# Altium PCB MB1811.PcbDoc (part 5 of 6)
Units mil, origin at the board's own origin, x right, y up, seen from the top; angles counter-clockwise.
Board outline 3480.3 x 4291.34 mil, 4 copper layers (Top Layer, L2_VCC, L3_GND, Bottom Layer), stack 30.59 mil thick; 371 components, 285 nets, 1369 pads, 606 vias.
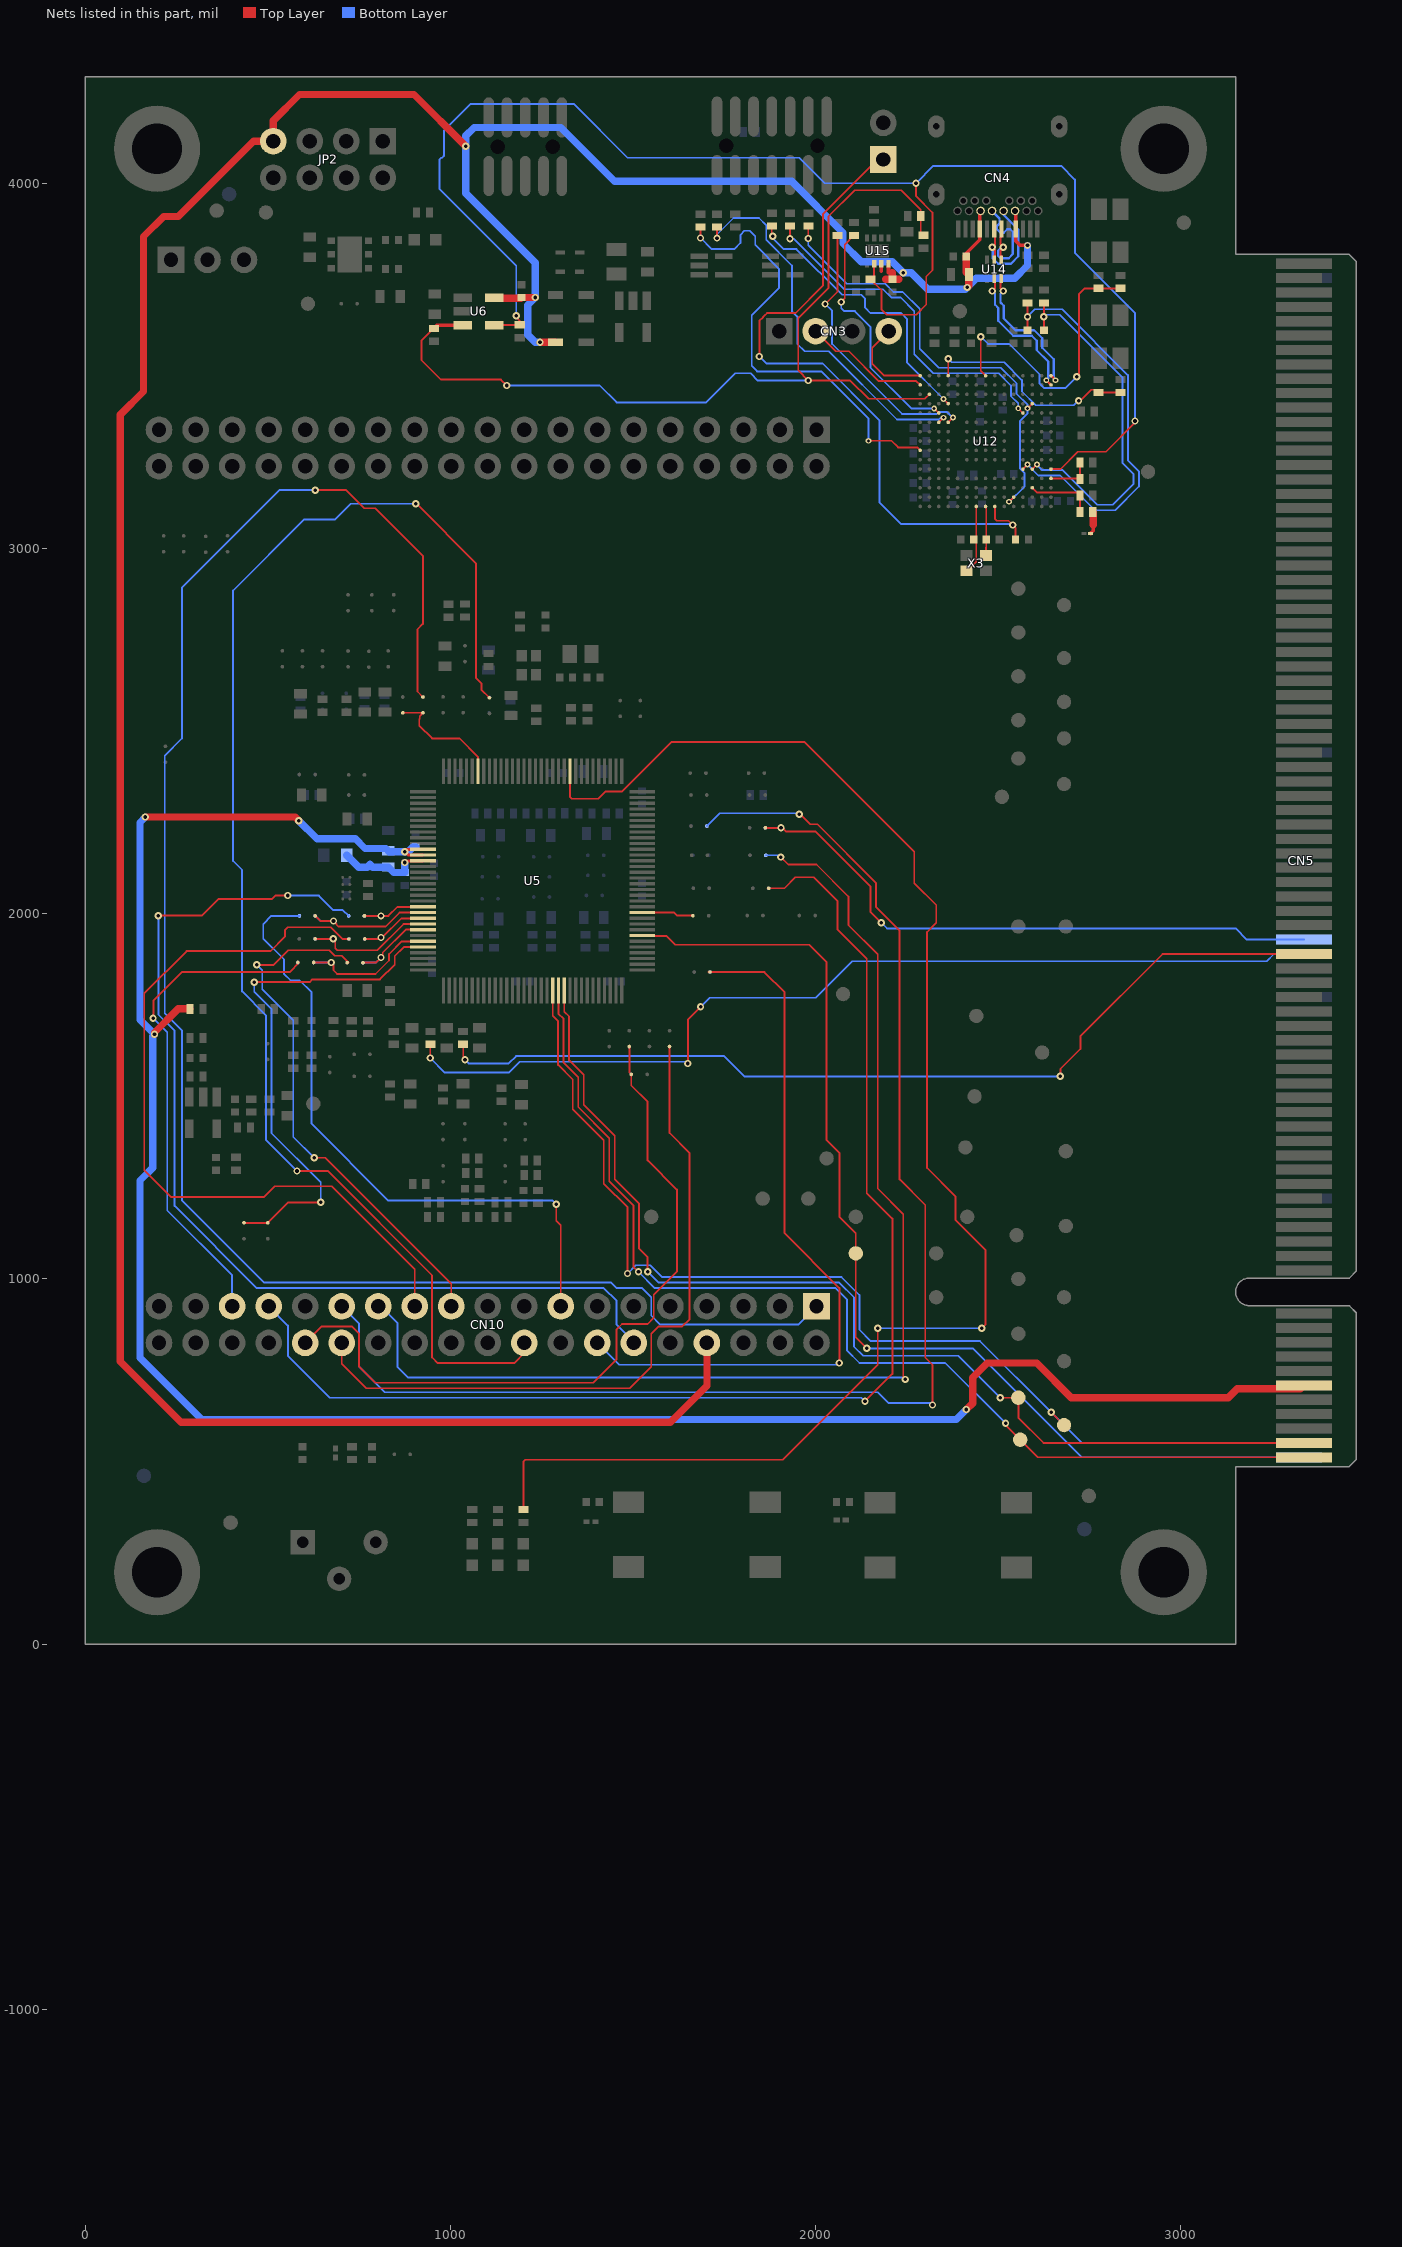
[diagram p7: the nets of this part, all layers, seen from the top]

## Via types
v1: diameter 20, hole 10, Top Layer to Bottom Layer, tented both sides, 524 vias
v2: diameter 16, hole 8, Top Layer to Bottom Layer, tented both sides, 82 vias

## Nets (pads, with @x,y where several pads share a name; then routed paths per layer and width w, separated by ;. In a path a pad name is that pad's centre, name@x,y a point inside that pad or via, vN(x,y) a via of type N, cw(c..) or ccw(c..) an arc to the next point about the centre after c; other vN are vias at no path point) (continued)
PE7: SB16.1 SB85.1 U5.53 | length 215.9
  Top Layer w5: SB16.1@764.67,1993.95 v1@809.93,1993.95 ; v1(809.95,1993.97) 830.29,1993.97 855.14,2018.82 U5.53@924.99,2018.83
  Bottom Layer w5: SB85.1@764.67,1993.95 v1@809.93,1993.95
PE8: SB8.1 SB89.1 U5.54 | length 379.6
  Top Layer w5: SB8.1@629.99,1993.95 643.69,1980.25 v1(679.99,1980.25) 688.24,1972 688.24,1970.32 693.8,1964.76 822.3,1964.76 860.61,2003.07 U5.54@924.99,2003.09
  Bottom Layer w5: SB89.1@629.98,1993.94 643.67,1980.25 v1(679.99,1980.25)
PE9: SB18.1 SB84.1 U5.55 | length 230
  Top Layer w5: SB18.1@764.99,1931.07 806.05,1931.07 v1(809.99,1935.01) 813.77,1935.01 866.08,1987.32 U5.55@924.99,1987.34
  Bottom Layer w5: SB84.1@764.98,1931.06 806.04,1931.06 v1(809.99,1935.01)
PE10: SB6.1 SB90.1 U5.56 | length 398.8
  Top Layer w5: SB6.1@629.67,1931.07 v1(678.93,1931.07) 684.99,1925.01 684.99,1905.01 689.99,1900.01 799.99,1900.01 871.56,1971.58 U5.56@924.99,1971.59
  Bottom Layer w5: SB90.1@629.67,1931.07 v1(678.93,1931.07)
PE11: SB13.1 SB88.1 U5.57 | length 254.4
  Top Layer w5: SB13.1@764.67,1866.07 796.05,1866.07 v1(809.99,1880.01) 814.99,1885.01 814.99,1893.79 877.78,1956.58 924.24,1956.58 U5.57@924.99,1955.84
  Bottom Layer w5: SB88.1@764.67,1866.06 796.04,1866.06 v1(809.99,1880.01)
PE13: SB5.1 SB92.1 U5.59 | length 408.2
  Top Layer w5: SB5.1@629.68,1866.54 v1(673.46,1866.54) 679.99,1860.01 679.99,1845.01 689.99,1835.01 794.99,1835.01 831.84,1871.86 831.84,1889.42 866.75,1924.33 U5.59@924.99,1924.35
  Bottom Layer w5: SB92.1@629.68,1866.54 v1(673.46,1866.54)
PE14: SB2.2 SB3.2 U5.60 | length 1428.5
  Top Layer w5: SB2.2@433.61,1153.63 SB3.2@499.99,1153.63 556.06,1209.7 v1(644.87,1209.7) ; v1(462.87,1812.7) 614.88,1812.7 622.19,1820.01 807.19,1820.01 847.84,1860.66 847.84,1884.2 872.22,1908.58 U5.60@924.99,1908.6
  Bottom Layer w5: v1(462.87,1812.7) 462.87,1786.7 509.99,1739.58 509.99,1399.58 644.87,1264.7 v1(644.87,1209.7)
PF2: SB28.1 SB29.1 U5.26 | length 337.5
  Top Layer w5: U5.26@1075.38,2389.7 1075.38,2429.62 1024.99,2480.01 949.87,2480.01 914.87,2515.01 914.87,2532.52 916.03,2533.68 916.03,2541.18 SB28.1@924.87,2550.02 877.37,2550.01 ; 877.37,2550.01 SB29.1@869.87,2550.01 877.37,2550.01
PF3: R32.2 U5.10 | length 4209.7
  Top Layer w5: R32.2@1199.83,368.86 1199.83,500.01 1204.83,505.01 1910,505.01 2169.99,765 v1(2169.99,864.7) ; U5.10@1327.35,2389.7 1327.35,2319.7 1332.35,2314.7 1404.68,2314.7 1424.99,2335.01 1469.99,2335.01 1604.99,2470.01 1969.99,2470.01 2269.99,2170.01 2269.99,2083.79 2329.99,2023.79 2329.99,1975.01 2304.99,1950.01 2304.99,1303.78 2382.8,1225.97 2382.8,1162.19 2464.87,1080.12 2464.87,875.01 v1(2454.87,865.01)
  Bottom Layer w5: v1(2169.99,864.7) 2170.3,865.01 v1(2454.87,865.01)
PFC_BKIN_OC: CN5.A35 SB56.2 SB68.2 | length 1684.6
  Top Layer w5: SB56.2@1862.42,2235 v1(1904.98,2235) 1909.56,2235 1919.86,2224.7 2000.29,2224.7 2149.99,2075 2149.99,2005.01 v1(2179.99,1975.01)
  Bottom Layer w5: SB68.2@1862.42,2235 v1(1904.98,2235) ; v1(2179.99,1975.01) 2195.3,1959.7 3150.3,1959.7 3180.86,1929.14 CN5.A35@3336.8,1929.14
PFC_Current1_C: CN5.A34 R16.1 | length 2654.6
  Top Layer w5: v1(944.99,1605.01) R16.1@944.99,1642.29 ; v1(1650.09,1589.91) 1650.09,1710.11 v1(1684.99,1745.01)
  Bottom Layer w5: v1(944.99,1605.01) 984.99,1565.01 1159.99,1565.01 1189.68,1594.7 1645.3,1594.7 v1(1650.09,1589.91) ; v1(1684.99,1745.01) 1709.68,1769.7 1999.88,1769.7 2099.88,1869.7 3234.87,1869.7 3254.95,1889.78 CN5.A34@3336.8,1889.77
PFC_Current2_C: CN5.B34 R21.1 | length 2547.6
  Top Layer w5: R21.1@1034.99,1642.29 1034.99,1605.01 v1(1039.99,1600.01) ; v1(2669.99,1554.7) 2669.99,1574.82 2724.87,1629.7 2724.87,1664.69 2949.95,1889.77 CN5.B34@3336.8,1889.77
  Bottom Layer w5: v1(1039.99,1600.01) 1049.99,1590.01 1159.99,1590.01 1179.99,1610.01 1749.55,1610.01 1804.86,1554.7 v1(2669.99,1554.7)
PG2: CN5.A02 TP31.1 U5.84 | length 3027
  Top Layer w5: U5.84@1280.11,1789.7 1280.11,1720.99 1294.99,1706.11 1294.99,1586.11 1334.99,1546.11 1334.99,1464.57 1419.99,1379.57 1419.99,1261.17 1484.99,1196.17 v1(1484.99,1015.01) ; v1(2644.99,635) TP31.1@2679.99,600
  Bottom Layer w5: v1(1484.99,1015.01) 1506.45,1036.46 1506.69,1036.46 1507.74,1037.51 1547.24,1037.51 1579.74,1005.01 2070.79,1005.01 2119.99,955.81 2119.99,861.23 2151.21,830.01 2449.98,830.01 v1(2644.99,635) 2728.8,551.19 CN5.A02@3336.8,551.19
PG3: CN5.B01 TP29.1 U5.85 | length 2977.5
  Top Layer w5: U5.85@1295.86,1789.7 1295.85,1726.47 1309.99,1712.33 1309.99,1592.33 1349.99,1552.33 1349.99,1470.79 1434.99,1385.79 1434.99,1267.39 1501.11,1201.27 1501.11,1033.89 v1(1514.99,1020.01) ; v1(2519.99,605.01) 2519.99,600.01 TP29.1@2559.99,560.01 2608.18,511.82 CN5.B01@3336.8,511.82
  Bottom Layer w5: v1(1514.99,1020.01) 1559.99,975.01 2054.55,975.01 2085.42,944.14 2085.42,804.57 2119.98,770.01 2354.99,770.01 v1(2519.99,605.01)
PG4: CN5.B02 TP20.1 U5.86 | length 2966.4
  Top Layer w5: U5.86@1311.6,1789.7 1311.6,1731.94 1324.99,1718.55 1324.99,1598.55 1364.99,1558.55 1364.99,1477.01 1449.99,1392.01 1449.99,1273.61 1516.11,1207.49 1516.11,1083.89 1539.99,1060.01 v1(1539.99,1020.01) ; v1(2504.99,675) TP20.1@2554.99,675 2554.99,620 2623.8,551.19 CN5.B02@3336.8,551.19
  Bottom Layer w5: v1(1539.99,1020.01) 1569.99,990.01 2064.57,990.01 2104.99,949.59 2104.99,815.01 2129.99,790.01 2389.98,790.01 v1(2504.99,675)
PG5: CN5.A01 TP10.1 U5.103 | length 2944.5
  Top Layer w5: U5.103@1524.99,1940.09 1525.74,1939.33 1591.68,1939.33 1592.43,1938.58 1592.52,1938.58 1616.09,1915.01 1982.55,1915.01 2029.99,1867.57 2029.99,1380.01 2064.99,1345.01 2064.99,1170.01 2109.99,1125.01 TP10.1@2109.99,1070.01 2109.99,840.01 v1(2139.99,810.01)
  Bottom Layer w5: v1(2139.99,810.01) 2429.99,810.01 2728.18,511.82 CN5.A01@3322.83,511.82
PG9: SB51.1 U5.107 | length 142.4
  Top Layer w5: U5.107@1524.99,2003.09 1612.83,2003.07 1617.32,1998.58 1617.4,1998.58 1621.29,1994.69 SB51.1@1663.93,1994.69
R1_PF2: CN10.1 SB28.2 | length 4889
  Top Layer w5: v1(629.87,3159.7) 714.87,3159.7 764.56,3110.01 794.56,3110.01 924.87,2979.7 924.87,2793.49 909.87,2778.49 909.87,2608.32 SB28.2@924.87,2593.32 SB28.2@924.99,2593.44
  Bottom Layer w5: v1(629.87,3159.7) 531.7,3159.7 264.87,2892.87 264.87,2479.7 217.99,2432.82 217.99,1727.8 264.87,1680.92 264.87,1215.13 489.99,990.01 1439.99,990.01 1454.99,975.01 1524.99,975.01 1549.99,950.01 1549.99,900.01 1574.99,875.01 1952.38,875.01 CN10.1@2002.37,925
R12_PE7: CN10.12 SB85.2 | length 2832.2
  Top Layer w5: v1(200.49,1994.7) 319.87,1994.7 365.87,2040.7 511.87,2040.7 520.87,2049.7 v1(554.87,2049.7)
  Bottom Layer w5: v1(200.49,1994.7) 200.49,1724.08 244.87,1679.7 244.87,1200.13 469.99,975.01 1419.99,975.01 1454.99,940.01 1454.99,875.01 1502.37,827.63 CN10.12@1502.37,825 ; v1(554.87,2049.7) 639.86,2049.7 679.55,2010.01 705.31,2010.01 SB85.2@721.37,1993.95
R14_PA15: CN10.14 SB53.2 | length 1997.7
  Top Layer w5: SB53.2@1706.92,1840.33 SB53.2@1710.86,1840.33 1859.68,1840.33 1914.99,1785.02 1914.99,1125.01 2064.99,975.01 v1(2064.99,770.01)
  Bottom Layer w5: CN10.14@1402.37,825 1462.36,765.01 2059.99,765.01 v1(2064.99,770.01)
R15_PE8: CN10.15 SB89.2 | length 1770.1
  Top Layer w5: v1(1289.87,1204.7) 1289.87,1159.7 1302.37,1147.2 CN10.15@1302.37,925
  Bottom Layer w5: SB89.2@586.68,1993.94 510.12,1993.94 487.87,1971.69 487.87,1931.7 544.87,1874.7 544.87,1834.69 562.37,1817.19 587.37,1817.19 619.87,1784.69 619.87,1425.13 830.3,1214.7 844.3,1214.7 844.49,1214.51 1280.06,1214.51 v1(1289.87,1204.7)
R18_PC0: CN10.18 SB14.2 | length 3886.6
  Top Layer w5: v1(579.87,1295.7) 663.88,1295.7 949.99,1009.59 949.99,785.01 965.3,769.7 1174.68,769.7 1202.37,797.39 CN10.18@1202.37,825 ; v1(904.87,3122.2) 907.37,3122.2 1069.87,2959.7 1069.87,2645.92 1084.87,2630.92 1084.87,2613.75 SB14.2@1107,2591.62
  Bottom Layer w5: v1(579.87,1295.7) 494.99,1380.58 494.99,1722.23 429.87,1787.35 429.87,2119.7 404.87,2144.7 404.87,2884.7 599.87,3079.7 684.87,3079.7 727.37,3122.2 v1(904.87,3122.2)
R21_PE11: CN10.21 SB13.2 | length 1455.9
  Top Layer w5: v1(469.87,1860.01) 515.99,1860.01 555.99,1900.01 668.77,1900.01 683.77,1885.01 702.43,1885.01 SB13.2@721.38,1866.06 ; v1(626.87,1331.7) 657.87,1331.7 1002.37,987.2 CN10.21@1002.37,925
  Bottom Layer w5: v1(469.87,1860.01) 484.87,1845.01 484.87,1793.65 569.87,1708.65 569.87,1388.7 v1(626.87,1331.7)
R23_PE9: CN10.23 SB18.2 | length 2120.1
  Top Layer w5: SB18.2@721.06,1931.06 703.94,1931.06 672.25,1962.75 554.92,1962.75 546.87,1954.7 546.87,1936.89 507.49,1897.51 277.67,1897.51 161.99,1781.83 161.99,1298.01 235.99,1224.01 489.18,1224.01 518.87,1253.7 674.86,1253.7 902.37,1026.19 CN10.23@902.37,925
R25_PD7: CN10.25 SB67.2 | length 3255.1
  Top Layer w5: v1(1904.87,2155.01) 1925.18,2134.7 2002.3,2134.7 2089.99,2047.01 2089.99,1968.67 2169.99,1888.67 2169.99,1247.68 2239.99,1177.68 2239.99,730.01 v1(2244.99,725.01)
  Bottom Layer w5: CN10.25@802.37,925 810,925 854.99,880.01 854.99,760.01 884.99,730.01 2239.99,730.01 v1(2244.99,725.01) ; SB67.2@1863.62,2160.01 1899.87,2160.01 v1(1904.87,2155.01)
R27_PB6: CN10.27 SB72.2 | length 3848.5
  Top Layer w5: v1(1954.87,2272.2) 1957.68,2272.2 1984.87,2245.01 2004.99,2245.01 2164.99,2085.01 2164.99,2018.79 2229.99,1953.79 2229.99,1272.56 2299.99,1202.56 2299.99,785.01 2319.99,765.01 v1(2319.99,655.01)
  Bottom Layer w5: CN10.27@702.37,925 749.99,877.38 749.99,760.01 819.99,690.01 2169.98,690.01 2199.98,660.01 2314.99,660.01 v1(2319.99,655.01) ; SB72.2@1702.11,2240 1737.12,2275.01 1952.06,2275.01 v1(1954.87,2272.2)
R28_PA12: CN10.28 SB46.2 | length 1938
  Top Layer w5: CN10.28@702.37,825 702.37,767.64 769.31,700.7 1490.68,700.7 1549.99,760.01 1549.99,850.01 1569.99,870.01 1634.99,870.01 1654.99,890.01 1654.99,1344.58 1599.99,1399.58 SB46.2@1599.99,1636.38
R30_PA11: CN10.30 SB42.1 SB43.2 | length 2033.9
  Top Layer w5: CN10.30@602.37,825 647.38,870.01 729.99,870.01 749.99,850.01 749.99,760.01 793.99,716.01 1390.99,716.01 1454.99,780.01 1454.99,861.82 1469.87,876.7 1539.87,876.7 1556.87,893.7 1556.87,956.89 1619.99,1020.01 1619.99,1244.57 1539.99,1324.57 1539.99,1485.01 1495.31,1529.69 SB42.1@1495.31,1560.01 1489.99,1565.33 SB43.2@1489.99,1636.38
R31_PD4: CN10.31 SB59.2 | length 3483.3
  Top Layer w5: SB59.2@1867.39,2069.69 SB59.2@1871.33,2069.69 1914.67,2069.69 1944.68,2099.7 1994.86,2099.7 2059.99,2034.57 2059.99,1956.23 2139.99,1876.23 2139.99,1235.24 2209.99,1165.24 2209.99,740.01 v1(2134.99,665.01)
  Bottom Layer w5: CN10.31@502.37,925 554.99,872.38 554.99,790.01 669.99,675.01 2124.99,675.01 v1(2134.99,665.01)
R33_PE13: CN10.33 SB5.2 | length 1369.7
  Top Layer w5: v1(186.07,1714.15) 186.87,1714.95 186.87,1761.89 264.99,1840.01 559.84,1840.01 SB5.2@586.37,1866.54
  Bottom Layer w5: v1(186.07,1714.15) 224.87,1675.35 224.87,1187.5 402.37,1010 CN10.33@402.37,925
STLK_LED: R46.1 R47.2 U12.D15 | length 610.6
  Top Layer w5: U12.D15@2362.81,3473.25 v1(2362.81,3519.7) ; v1(2719.87,3404.7) 2724.87,3404.7 2754.87,3434.7 2767.15,3434.7 R46.1@2774.87,3426.98 R47.2@2834.87,3426.99
  Bottom Layer w5: v1(2362.81,3519.7) 2372.81,3509.7 2516.2,3509.7 2564.86,3461.04 2564.86,3458.25 2564.87,3429.7 2602.57,3392 2707.17,3392 v1(2719.87,3404.7)
STLK_NRST: C48.2 JP3.1 U12.J1 | length 1884.5
  Top Layer w5: v1(1845.85,3525.67) 1845.85,3623.38 1856.07,3633.6 1856.07,3634.52 1860.47,3638.92 1861.39,3638.92 1867.17,3644.7 1945.45,3644.7 2019.87,3719.12 2019.87,3915.02 2169.86,4065.01 JP3.1@2184.99,4065.01 ; U12.J1@2490.77,3114.98 2490.76,3081.09 2495.85,3076 2528.02,3076 v1(2539.89,3064.13) 2547.15,3056.87 C48.2@2547.15,3024.7
  Bottom Layer w5: v1(1845.85,3525.67) 1864.87,3506.65 2018.82,3506.65 2174.47,3351 2174.47,3126.1 2233.94,3066.63 2536.5,3066.63 2539,3064.13 v1(2539.89,3064.13)
STLK_OSC_IN: C39.1 U12.G1 X3.1 | length 194
  Top Layer w5: X3.1@2413.29,2939.03 2415.25,2939.03 2439.87,2963.65 2439.87,3017.41 C39.1@2432.59,3024.7 2439.58,3031.7 U12.G1@2439.58,3114.98
STLK_OSC_OUT: C44.2 U12.H1 X3.3 | length 135.7
  Top Layer w5: U12.H1@2465.18,3114.98 2467.15,3113 2467.15,3003.35 2466.44,3002.64 X3.3@2466.44,2980.37
STLK_SWCLK: CN3.2 U12.A14 | length 347.1
  Top Layer w5: CN3.2@1999.99,3595 2055.29,3539.7 2091.37,3539.7 2172.82,3458.25 2275.45,3458.25 U12.A14@2286.04,3447.66
STLK_SWDIO: CN3.4 U12.A15 | length 252.3
  Top Layer w5: CN3.4@2199.99,3595 2154.87,3549.88 2154.87,3506.2 2187.82,3473.25 U12.A15@2286.04,3473.25
STLK_UCPD_CC1_C: C34.1 R54.1 U12.M5 | length 1151.7
  Top Layer w5: U12.M5@2567.54,3217.34 v2(2580.21,3230.03) ; C34.1@2579.87,3597.42 v1(2579.87,3634.7) R54.1@2579.87,3671.99
  Bottom Layer w5: v1(2579.87,3634.7) 2599.87,3654.7 2674.87,3654.7 2854.87,3474.7 2854.87,3240.92 2884.87,3210.92 2884.87,3169.7 2819.87,3104.7 2764.87,3104.7 2669.87,3199.7 2609.86,3199.7 2580.21,3229.35 v2(2580.21,3230.03)
STLK_UCPD_CC2_C: C36.1 R55.1 U12.N5 | length 1019.3
  Top Layer w5: U12.N5@2593.13,3217.34 v2(2605.8,3230.03) ; C36.1@2624.87,3597.42 v1(2624.87,3634.7) R55.1@2624.87,3671.98
  Bottom Layer w5: v2(2605.8,3230.03) 2605.8,3228.77 2619.87,3214.7 2676.09,3214.7 2771.09,3119.7 2813.65,3119.7 2869.87,3175.92 2869.87,3204.7 2839.87,3234.7 2839.87,3468.48 2668.65,3639.7 2629.87,3639.7 v1(2624.87,3634.7)
STLK_USB_CN_N: CN4.A7 CN4.B7 U14.2 | length 349
  Top Layer w6.1: U14.2@2488.86,3790.29 2488.87,3800.01 2491.21,3802.35 2491.21,3817.04 v1(2483.55,3824.7) 2491.23,3832.38 2491.23,3853.33 2488.89,3855.67 CN4.A7@2488.89,3874.79
  Bottom Layer w6.1: v1(2483.55,3824.7) 2484.87,3823.38 2484.87,3794.58 2499.75,3779.7 2534.87,3779.7 2554.87,3799.7 2554.87,3873.34 2514.48,3913.73 CN4.B7@2514.48,3924
STLK_USB_CN_P: CN4.A6 CN4.B6 U14.1 | length 348.5
  Top Layer w6.1: U14.1@2508.55,3790.29 2508.55,3799.69 2506.21,3802.03 2506.21,3817.36 v1(2513.55,3824.7) 2506.23,3832.02 2506.23,3851.05 2508.57,3853.39 CN4.A6@2508.57,3874.79
  Bottom Layer w6.1: CN4.B6@2482.98,3924 2503.58,3903.41 2503.58,3889.48 2496.65,3882.55 2496.65,3873.91 2506.22,3864.34 2514.84,3864.34 2524.41,3873.91 2533.08,3873.91 2539.87,3867.12 2539.87,3805.92 2528.65,3794.7 2505.97,3794.7 2499.87,3800.8 2499.87,3815.49 2509.08,3824.7 v1(2513.55,3824.7)
STLK_USB_N: U12.R14 U14.5 | length 396.3
  Top Layer w6.1: v1(2483.87,3704.7) 2491.21,3712.04 2491.21,3727.37 2488.87,3729.71 U14.5@2488.86,3739.11 ; v2(2631.51,3460.45) U12.R14@2644.31,3447.66
  Bottom Layer w6.1: v1(2483.87,3704.7) 2491.37,3697.2 2491.37,3666.98 2499.87,3658.48 2499.87,3623.48 2540.75,3582.6 2591.95,3582.6 2605.57,3568.98 2605.57,3543.01 2636.87,3511.71 2636.87,3465.81 v2(2631.51,3460.45)
STLK_USB_P: U12.R15 U14.6 | length 396.4
  Top Layer w6.1: U14.6@2508.55,3739.11 2508.55,3729.39 2506.21,3727.05 2506.21,3712.36 v1(2513.87,3704.7) ; U12.R15@2644.31,3473.25 v2(2657.09,3460.46)
  Bottom Layer w6.1: v1(2513.87,3704.7) 2506.37,3697.2 2506.37,3673.2 2514.87,3664.7 2514.87,3629.7 2546.97,3597.6 2598.17,3597.6 2620.57,3575.2 2620.57,3549.23 2651.87,3517.93 2651.87,3465.68 v2(2657.09,3460.46)
STLK_VCP_RX: R41.1 U12.C10 | length 1067.7
  Top Layer w5: v1(1729.92,3849.75) R41.1@1729.92,3879.95 ; U12.C10@2337.22,3345.3 v2(2349.9,3357.98)
  Bottom Layer w5: v1(1729.92,3849.75) 1729.92,3859.55 1775.07,3904.7 1844.87,3904.7 1864.87,3884.7 1864.87,3844.7 1934.87,3774.7 1934.87,3649.7 1949.87,3634.7 1949.87,3559.7 1969.87,3539.7 2036.09,3539.7 2222.72,3353.07 2337.19,3353.07 2340.45,3356.33 2342.72,3356.33 2344.37,3357.98 v2(2349.9,3357.98)
STLK_VCP_TX: R40.1 U12.A7 | length 1237.5
  Top Layer w5: v1(1684.92,3850.01) R40.1@1684.92,3879.97 ; v2(2144.87,3294.7) 2207.67,3294.7 2225.87,3276.5 2278.07,3276.5 U12.A7@2286.04,3268.52
  Bottom Layer w5: v1(1684.92,3850.01) 1715.23,3819.7 1777.37,3819.7 1794.27,3836.6 1794.27,3858.3 1794.87,3858.9 1794.87,3859.45 1805.12,3869.7 1819.87,3869.7 1834.87,3854.7 1834.87,3830.92 1869.87,3795.92 1869.87,3794.7 1899.87,3764.7 1899.87,3713.17 1824.87,3638.17 1824.87,3499.7 1839.87,3484.7 2014.87,3484.7 2144.87,3354.7 v2(2144.87,3294.7)
T_PWR_EN: R34.2 R87.2 U6.4 U12.R5 U15.2 | length 4238.7
  Top Layer w5: U6.4@1120.43,3611.54 R34.2@1189,3611.54 ; v1(1180.27,3637.45) 1180.27,3632.8 1189,3624.07 R34.2@1189,3611.54 ; R34.2@1189.87,3612.41 R34.2@1189,3611.54 ; U15.2@2160.04,3779.27 2160.03,3747.58 R87.2@2149.87,3737.42 2149.99,3737.42 2179.87,3707.54 2179.87,3654.7 2194.87,3639.7 2274.87,3639.7 2303,3667.83 2303,3744.65 2319.87,3761.52 2319.87,3919.7 2274.87,3964.7 v1(2274.87,3999.7) ; U12.R5@2644.31,3217.34 2670.41,3217.34 2717.77,3264.7 2794.87,3264.7 2874.22,3344.05 v1(2874.22,3349.05)
  Bottom Layer w5: v1(1180.27,3637.45) 1180.27,3774.3 969.87,3984.7 969.87,4064.7 974.87,4069.7 977.37,4069.7 982.37,4074.7 982.37,4144.02 1055.55,4217.2 1337.37,4217.2 1484.87,4069.7 1954.87,4069.7 2024.87,3999.7 v1(2274.87,3999.7) 2322.37,4047.2 2672.37,4047.2 2709.87,4009.7 2709.87,3809.7 2874.22,3645.35 v1(2874.22,3349.05)
T_PWR_EXT: R50.1 R51.1 U12.R4 | length 124.9
  Top Layer w5: U12.R4@2644.3,3191.75 2722.18,3191.75 R51.1@2723.63,3190.3 R50.1@2723.64,3235.3
T_PWR_INT: R30.2 R58.2 R59.1 U6.3 U12.B13 | length 2561.7
  Top Layer w5: R30.2@954.87,3602.41 920.77,3568.31 920.77,3515.9 974.37,3462.3 1138.47,3462.3 v1(1154.47,3446.3) ; R59.1@2294.87,3857.42 2287.59,3864.7 2287.59,3926.98 2233.87,3980.7 2106.77,3980.7 2034.87,3908.8 2034.87,3712.9 1952.27,3630.3 1952.27,3487.3 v1(1979.87,3459.7) 2094.87,3459.7 2144.92,3409.65 2299.21,3409.65 U12.B13@2311.63,3422.07
  Top Layer w10: R30.2@954.87,3602.41 964,3611.54 U6.3@1033.81,3611.54
  Bottom Layer w5: v1(1154.47,3446.3) 1408.27,3446.3 1454.87,3399.7 1700.37,3399.7 1780.37,3479.7 1822,3479.7 1842,3459.7 v1(1979.87,3459.7)
T_PWR_LED: R88.2 R89.2 U12.H15 | length 809.1
  Top Layer w5: v1(2451.97,3579.7) 2451.97,3486.45 U12.H15@2465.18,3473.25 ; v1(2714.87,3469.7) 2720.67,3475.5 2720.67,3695.5 2737.15,3711.98 R88.2@2834.87,3711.98
  Bottom Layer w5: v1(2451.97,3579.7) 2471.97,3559.7 2529.86,3559.7 2613.27,3476.29 2613.27,3451.3 2624.87,3439.7 2684.87,3439.7 v1(2714.87,3469.7)
T_PWR_SEL1: R63.2 U12.D10 | length 756
  Top Layer w5: v1(2025.87,3669.3) 2059.87,3703.3 R63.2@2059.87,3856.98 ; U12.D10@2362.81,3345.3 v2(2375.6,3358.09)
  Bottom Layer w5: v1(2025.87,3669.3) 2044.87,3650.3 2044.87,3559.7 2236.5,3368.07 2330.97,3368.07 2336.38,3373.48 2360.21,3373.48 v2(2375.6,3358.09)
T_PWR_SEL2: R84.2 U12.C11 | length 665.1
  Top Layer w5: v1(2069.87,3674.7) 2079.87,3684.7 2079.87,3831.98 R84.2@2104.87,3856.98 ; v2(2324.54,3383.57) U12.C11@2337.22,3370.89
  Bottom Layer w5: v1(2069.87,3674.7) 2069.87,3658.2 2078.37,3649.7 2107.4,3649.7 2149.87,3607.23 2149.87,3495.42 2261.72,3383.57 v2(2324.54,3383.57)
T_SWCLK: R44.1 U12.M11 | length 963.6
  Top Layer w5: R44.1@1929.92,3882.68 1929.92,3847.98 v1(1929.99,3847.91) ; v2(2554.74,3383.68) U12.M11@2567.54,3370.89
  Bottom Layer w5: v1(1929.99,3847.91) 1940.43,3847.91 2078.64,3709.7 2184.39,3709.7 2206.89,3687.2 2232.37,3687.2 2269.87,3649.7 2269.87,3532 2322.17,3479.7 2500.97,3479.7 2534.87,3445.8 2534.87,3417.26 2554.74,3397.39 v2(2554.74,3383.68)
T_SWDIO: R45.1 U12.L2 U12.N12 | length 1248.4
  Top Layer w5: v1(1979.92,3848.7) R45.1@1979.92,3882.68 ; v2(2529.26,3127.89) U12.L2@2541.95,3140.57 ; v2(2580.33,3383.69) U12.N12@2593.13,3396.48
  Bottom Layer w5: v1(1979.92,3848.7) 1979.92,3829.64 2084.86,3724.7 2190.61,3724.7 2213.11,3702.2 2238.59,3702.2 2284.87,3655.92 2284.87,3546.4 2336.57,3494.7 2507.19,3494.7 2549.87,3452.02 2549.87,3423.48 2580.33,3393.02 v2(2580.33,3383.69) 2580.33,3370.17 2559.92,3349.76 2559.92,3218.3 2572.23,3205.99 2572.23,3169.6 2530.52,3127.89 v2(2529.26,3127.89)
T_SWO: R43.1 U12.D12 | length 786.9
  Top Layer w5: R43.1@1879.92,3882.68 1879.92,3857.15 v1(1882.37,3854.7) ; v2(2350.02,3409.27) U12.D12@2362.81,3396.48
  Bottom Layer w5: v1(1882.37,3854.7) 1882.37,3849.75 1912.42,3819.7 1947.42,3819.7 2072.42,3694.7 2124.87,3694.7 2135.37,3684.2 2135.37,3659.2 2149.87,3644.7 2234.27,3644.7 2249.87,3629.1 2249.87,3509.42 v2(2350.02,3409.27)
T_VCC: LNK1.2 R53.2 | length 63.1
  Top Layer w10: LNK1.2@2752.73,3040.7 2760.18,3048.15 2760.18,3064.58
  Top Layer w20: R53.2@2759.08,3100.3 2760.18,3099.19 2760.18,3064.58
T_VCC_AIN: R52.1 R53.1 U12.N3 | length 184.2
  Top Layer w5: U12.N3@2593.13,3166.16 2605.91,3153.37 2715.56,3153.37 R52.1@2723.63,3145.3 R53.1@2723.64,3100.3
VBUS_STLK: C27.2 C42.1 C46.2 CN4.A4 CN4.A9 CN4.B4 CN4.B9 CN10.8 D5.1 JP2.7 U6.5 U13.1 U15.3 U15.4 | length 9183.2
  Top Layer w10: U15.3@2179.72,3779.27 2179.72,3759.85 2179.87,3759.7 ; U15.4@2199.41,3779.27 2199.4,3754.95 2199.87,3754.48 ; C42.1@2412.59,3799.7 2412.59,3808.42 2449.52,3845.35 2449.52,3922.04 CN4.B4@2451.49,3924 ; CN4.B9@2545.97,3924 2547.94,3922.03 2547.94,3841.63 2559.87,3829.7 v1(2579.87,3829.7)
  Top Layer w20: v1(1042.14,4101.24) 900.48,4242.9 587.07,4242.9 514.99,4170.82 JP2.7@514.99,4115.01 461.02,4115.01 255,3909 215,3909 159.99,3853.98 159.99,3429.81 95.99,3365.81 95.99,774.01 262.3,607.7 1602.68,607.7 1702.37,707.39 CN10.8@1702.37,825 ; U6.5@1120.43,3686.34 1121.76,3685 1192.89,3685 C27.2@1194.87,3686.98 v1(1232.67,3686.98) ; v1(1245.3,3564.7) D5.1@1287.75,3564.7 ; 2191.82,3737.42 C46.2@2209.87,3737.42 ; 2209.87,3754.48 C46.2@2209.87,3737.42 ; 2227.92,3737.42 C46.2@2209.87,3737.42 ; C42.1@2412.59,3799.7 2412.59,3756.59 U13.1@2419.49,3749.7 2419.48,3719.31 v1(2414.87,3714.7)
  Bottom Layer w20: v1(1245.3,3564.7) 1232.3,3564.7 1212,3585 1212,3666.31 v1(1232.67,3686.98) 1232.67,3781.9 1042.14,3972.43 v1(1042.14,4101.24) 1042.14,4129.54 1065.1,4152.5 1302.07,4152.5 1449.17,4005.4 1934.17,4005.4 2074.87,3864.7 2074.87,3834.7 2124.87,3784.7 2209.87,3784.7 v1(2239.87,3754.7) 2261.69,3754.7 2306.69,3709.7 2409.87,3709.7 v1(2414.87,3714.7) 2439.87,3739.7 2544.87,3739.7 2579.87,3774.7 v1(2579.87,3829.7)
VDDA: C82.2 C83.2 L1.1 SB83.1 U5.45 | length 263.8
  Top Layer w8: v1(874.95,2140.01) 879.74,2144.8 U5.45@924.99,2144.82
  Bottom Layer w20: L1.1@716.49,2160.01 748.92,2127.57 772.24,2127.57 SB83.1@779.99,2135.32 787.74,2127.57 C83.2@829.99,2127.57 844.83,2112.73 C82.2@874.99,2112.73 v1(874.95,2140.01) v1(874.95,2140.01)
VREF+: C81.2 C84.2 CN5.B06 R74.2 SB83.2 U5.43 U5.44 | length 5955.1
  Top Layer w8: U5.44@924.99,2160.55 884.45,2160.55 v1(874.99,2170.01) 881.28,2176.3 U5.43@924.99,2176.31
  Top Layer w20: v1(164.87,2264.7) 574.87,2264.7 v1(584.87,2254.7) ; v1(189.87,1669.7) 189.87,1674.7 254.87,1739.7 R74.2@287.16,1739.7 ; v1(2412.49,642.51) 2429.99,660.01 2429.99,730.01 2469.99,770.01 2604.99,770.01 2699.99,675.01 3129.99,675.01 3154.28,699.3 3327.43,699.3 CN5.B06@3336.8,708.67
  Bottom Layer w20: v1(164.87,2264.7) 149.99,2249.82 149.99,1709.58 v1(189.87,1669.7) 184.87,1664.7 184.87,1304.7 149.99,1269.82 149.99,784.57 319.55,615.01 2384.99,615.01 v1(2412.49,642.51) ; v1(584.87,2254.7) 634.56,2205.01 739.99,2205.01 766.37,2178.63 823.81,2178.63 832.43,2170.01 v1(874.99,2170.01) 884.99,2170.01 897.27,2182.29 C81.2@904.99,2182.29
pads on no net: CN1.1 CN1.2 CN1.4 CN1.6 CN1.7 CN1.8 CN1.10 CN1.NPTH1 CN1.NPTH2 CN2.1 CN2.2 CN2.9 CN2.10 CN2.NPTH1 CN2.NPTH2 CN4.A2 CN4.A3 CN4.A8 CN4.A10 CN4.A11 CN4.B2 CN4.B3 CN4.B8 CN4.B10 CN4.B11 CN5.A03 CN5.A04 CN5.A09 CN5.A10 CN5.A11 CN5.A61 CN5.A62 CN5.A63 CN5.A64 CN5.A70 CN5.A71 CN5.A72 CN5.A74 CN5.A75 CN5.A77 CN5.A78 CN5.A79 CN5.A80 CN5.A81 CN5.A82 CN5.B03 CN5.B04 CN5.B09 CN5.B10 CN5.B11 CN5.B61 CN5.B62 CN5.B63 CN5.B64 CN5.B73 CN5.B74 CN5.B75 CN7.4 CN7.7 CN7.8 CN7.9 CN7.10 CN7.11 CN7.13 CN7.14 CN7.15 CN7.19 CN7.21 CN7.24 CN7.25 CN7.26 CN7.27 CN7.29 CN7.33 CN10.2 CN10.3 CN10.4 CN10.5 CN10.7 CN10.9 CN10.10 CN10.11 CN10.13 CN10.16 CN10.17 CN10.19 CN10.35 CN10.36 CN10.37 CN10.38 U2.3 U2.5 U8.4 U12.A1 U12.A2 U12.A3 U12.A4 U12.A5 U12.A6 U12.A8 U12.A9 U12.A10 U12.A11 U12.A12 U12.A13 U12.B1 U12.B2 U12.B3 U12.B4 U12.B5 U12.B6 U12.B7 U12.B8 U12.B9 U12.B10 U12.B11 U12.B12 U12.B15 U12.C2 U12.C3 U12.C4 U12.C12 U12.C13 U12.C14 U12.C15 U12.D1 U12.D2 U12.D3 U12.D11 U12.D13 U12.D14 U12.E1 U12.E2 U12.E3 U12.E4 U12.E12 U12.E13 U12.E14 U12.E15 U12.F1 U12.F4 U12.F14 U12.G4 U12.G14 U12.G15 U12.H2 U12.H3 U12.H4 U12.H14 U12.J2 U12.J3 U12.J4 U12.K1 U12.K2 U12.K3 U12.K12 U12.K13 U12.K14 U12.K15 U12.L1 U12.L3 U12.L12 U12.L13 U12.L14 U12.L15 U12.M2 U12.M3 U12.M4 U12.M6 U12.M7 U12.M12 U12.M13 U12.M14 U12.M15 U12.N2 U12.N4 U12.N6 U12.N7 U12.N11 U12.N13 U12.N14 U12.N15 U12.P2 U12.P4 U12.P5 U12.P6 U12.P7 U12.P8 U12.P9 U12.P10 U12.P11 U12.P12 U12.P13 U12.P14 U12.P15 U12.R2 U12.R3 U12.R6 U12.R7 U12.R8 U12.R9 U12.R10 U12.R11 U12.R12 U14.4

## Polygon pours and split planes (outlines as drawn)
3V3_STLK on L2_VCC "L2_VCC-3V3_STLK" (solid, pour order 8): 478 vertices, not listed, extent 1593.99,2914.7 3129.55,4271.29
3V3 on L2_VCC "L2_VCC-3V3" (solid, pour order 6): 375 vertices, not listed, extent 20.04,20.03 3187,4271.29
NetR3_2 on Top Layer "TOP-NETR3_2" (solid, pour order 36): 133 vertices, not listed, extent 314.87,1644.7 519.87,1779.7
OPREF on Top Layer "TOP-OPREF" (solid, pour order 34): 130 vertices, not listed, extent 474.87,1439.7 669.87,1604.7
3V3_STLK on Top Layer "TOP-3V3_STLK" (solid, pour order 32): 1658.27,3552.8 1556.37,3654.7 1554.09,3654.7 1554.09,3708.62 1524.87,3708.62 1524.87,3739.54 1562.41,3739.54 1562.41,3774.7 1578.55,3774.7 1578.55,3760.65 1729.87,3609.34 1729.87,3594.7 1687.97,3552.8 1658.27,3552.8
3V3 on Top Layer "TOP-3V3" (solid, pour order 30): 359 vertices, not listed, extent 399.99,3630.01 704.99,3844.86
VBUS_STLK on Top Layer "TOP-VBUS_STLK" (solid, pour order 28): 49 vertices, not listed, extent 2174.87,3724.7 2259.87,3769.7
5V_STLK on Top Layer "TOP-5V_STLK" (solid, pour order 26): 2210.33,3854.7 2210.33,3864.99 2184.87,3864.99 2184.87,3944.7 2189.87,3949.7 2251.41,3949.7 2264.87,3936.24 2264.87,3928.5 2237.11,3928.5 2237.11,3890.9 2264.87,3890.9 2264.87,3884.88 2227.33,3884.88 2227.33,3854.7 2210.33,3854.7
5V on Top Layer "TOP-5V" (solid, pour order 24): 964 vertices, not listed, extent 429.99,3835.01 963.99,4047.51
GND on Top Layer "TOP-GND" (solid, pour order 22): 72 vertices, not listed, extent 1409.87,3799.7 1569.87,3874.7
GND on Top Layer "TOP-GND 1" (solid, pour order 20): 21 vertices, not listed, extent 569.99,3730.01 754.97,3811.01
GND on Top Layer "TOP-GND 2" (solid, pour order 18): 218 vertices, not listed, extent 1149.99,2490.01 1440.47,2860.01
NetC12_2 on Top Layer "TOP-NETC12_2" (solid, pour order 16): 118 vertices, not listed, extent 746.74,3645.01 829.99,3775.01
NetC1_2 on Top Layer "TOP-NETC1_2" (solid, pour order 14): 377.09,1484.7 377.09,1528.9 349.87,1528.9 349.87,1544.7 354.87,1549.7 449.87,1549.7 459.85,1539.72 459.85,1507.48 436.07,1507.48 436.07,1484.7 425.91,1484.7 425.91,1507.48 393.83,1507.48 393.83,1484.7 377.09,1484.7
NetC32_2 on Top Layer "TOP-NETC32_2" (solid, pour order 12): 113 vertices, not listed, extent 1339.87,3519.7 1574.87,3844.7
NetC86_2 on Top Layer "TOP-NETC86_2" (solid, pour order 10): 23 vertices, not listed, extent 234.87,1469.7 299.87,1694.7
GND on L3_GND "L3_GND-GND" (solid, pour order 4): 46 vertices, not listed, extent 20.03,20.03 3186.99,4271.29

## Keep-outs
Keep-Out Layer:
  lines w1: 3186.99,927.19 3460.61,927.19 3461.59,926.21 3480.29,907.5 3480.29,505.93 3460.61,486.24 3149.99,486.24 3149.99,0.01 -0.01,0.01 -0.01,4291.35 3149.58,4291.35 3149.58,3805.14 3460.61,3805.14 3461.59,3804.16 3480.29,3785.46 3480.29,1021.68 3461.59,1002.98 3460.61,1001.99 3186.99,1001.99

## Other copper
Top Layer:
  text ".Layer_Name" at 237.03,-1220.22 h118.11
  text ".GTL" at 1878.55,-1220.22 h118.11
L2_VCC:
  text "VCC" at 427,-1218 h118.11
  text ".G1" at 1924,-1222 h118.11
L3_GND:
  text ".G2" at 1926,-1214 h118.11
  text "GND" at 455,-1221 h118.11
Bottom Layer:
  text ".GBL" at 1437.48,-1221.48 h118.11
  text ".Layer_Name" at 3064.02,-1221.48 h118.11

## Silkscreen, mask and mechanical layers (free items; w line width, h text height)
Top Overlay:
  drawing of 382 lines, arcs and shapes, not listed
  text "P5V" at 826.83,4181.87 h55 r45
  text "CHG" at 519.83,4174.87 h55 r45
  text "E5V" at 622.83,4173.87 h55 r45
  text "STLK" at 717.83,4166.87 h55 r45
  text "USART" at 1428.83,4027.87 h55 r90
  text "STDC14" at 1680.83,4022.87 h55 r90
  text "USB STLK" at 2750.83,4011.87 h55 r90
  text "STLK_RST" at 2291,4003 h55 r90
  text "5V" at 547.83,3894.87 h55
  text "GND" at 145.83,3892.87 h55
  text "5V" at 1101.83,3837.87 h55
  text "<->" at 277,3693 h30
  text "0" at 200.83,3690.87 h55
  text "1" at 433.83,3686.87 h55
  text "BOOT0" at 240.83,3631.87 h55
  text "MCO" at 2266,3624 h45
  text "COM" at 2970.62,3519.87 h55 r90
  text "3V3" at 568.83,3512.87 h55 r90
  text "Morpho MC" at 58.83,3502.87 h55
  text "Reserved" at 1994.83,3488.87 h55
  text "PWR_STATUS" at 3067,3473 h55 r90
  text "PD3" at 1201.83,3384.87 h55 r45
  text "PA11" at 1904.83,3383.87 h55 r45
  text "PA7" at 203.83,3382.87 h55 r45
  text "3V3" at 1812.83,3382.87 h55 r45
  text "PA9" at 308.83,3381.87 h55 r45
  text "PG6" at 2007.83,3380.87 h55 r45
  text "PE5" at 905.83,3379.87 h55 r45
  text "PC9" at 2973.83,3136.87 h55
  text "PC4" at 136,3100 h45 r45
  text "5V" at 1176.83,3089.87 h55 r45
  text "3V3" at 1458.83,3089.87 h55 r45
  text "PC3" at 261,3088 h55 r45
  text "3V3" at 1268.83,3086.87 h55 r45
  text "PC2" at 669.83,3085.87 h55 r45
  text "PD0" at 1963.83,3084.87 h55 r45
  text "E5V" at 1761.83,3083.87 h55 r45
  text "PA3" at 558.83,3081.87 h55 r45
  text "PE10" at 343,3080 h45 r45
  text "PA5" at 472,3080 h55 r45
  text "GND" at 959.83,3077.87 h55 r45
  text "/PC4" at 387,3076 h45 r45
  text "/PE10" at 154,3074 h45 r45
  text "GND" at 1057.83,3070.87 h55 r45
  text "PF14" at 2623.83,2933.87 h55
  text "PF13" at 2389.83,2817.87 h55
  text "C" at 1488,2772 h551.18
  text "J" at 1876,2749 h700
  text "PF12" at 2387.83,2700.87 h55
  text "PF4" at 2550.83,2692.87 h55
  text "PF5" at 2394.83,2586.87 h55
  text "PF10" at 2523.83,2569.87 h55
  text "H" at 1935,2531 h551.18
  text "PE6" at 2391.83,2474.87 h55
  text "PF9" at 2624.83,2400.87 h55
  text "PG1" at 2392.83,2374.87 h55
  text "PD2" at 2377.83,2252.87 h55
  text "PG0" at 2619.83,2227.87 h55
  text "PE0" at 2392.83,1941.87 h55
  text "PE1" at 2607.83,1874.87 h55
  text "PG8" at 1925.83,1710.87 h55
  text "PE4" at 2288.83,1652.87 h55
  text "PF11" at 2492.83,1538.87 h55
  text "PE3" at 2280.83,1469.87 h55
  text "PC11" at 1917.83,1376.87 h55
  text "PA4" at 2536.83,1339.87 h55
  text "PE2" at 2247.83,1335.87 h55
  text "PG7" at 2129.83,1211.87 h55
  text "OPREF" at 636,1172 h55 r90
  text "PC12" at 2250.83,1146.87 h55
  text "PC8" at 1600.83,1144.87 h55
  text "PC10" at 1927.83,1139.87 h55
  text "PF6" at 1789.83,1138.87 h55
  text "PF7" at 2415.83,1042.87 h55
  text "PF8" at 2620.83,1022.87 h55
  text "PA0" at 2195.83,1009.87 h55
  text "PG5" at 2068.83,987.87 h55
  text "PA6" at 608,983 h55 r45
  text "PD4" at 509,982 h55 r45
  text "PE11" at 996,982 h55 r45
  text "PE9" at 906,981 h55 r45
  text "PB6" at 707,980 h55 r45
  text "PD7" at 818,980 h55 r45
  text "PE8" at 1312,980 h55 r45
  text "PF2" at 1995.83,979.87 h55 r45
  text "PE13" at 412.83,978.87 h55 r45
  text "PC7" at 2416.83,923.87 h55
  text "PB7" at 2199.83,845.87 h55
  text "PC6" at 2626.83,821.87 h55
  text "PD1" at 2421.83,775.87 h55
  text "GND" at 2770.83,748.87 h55
  text "PE7" at 1458.83,679.87 h55 r45
  text "PC0" at 1153.83,676.87 h55 r45
  text "GND" at 1049.83,672.87 h55 r45
  text "GND" at 442.83,670.87 h55 r45
  text "PA11" at 551.83,669.87 h55 r45
  text "Morpho MC" at 30.83,668.87 h55
  text "PA12" at 648.83,665.87 h55 r45
  text "PB9" at 846,666 h55 r45
  text "PA15" at 1345.83,662.87 h55 r45
  text "PE14" at 349.83,660.87 h55 r45
  text "/PB9" at 741.83,659.87 h55 r45
  text "PD15" at 938.83,658.87 h55 r45
  text "PE14" at 1759.83,656.87 h55 r45
  text "PG4" at 2421.83,629.87 h55
  text "PG2" at 2729.83,539.87 h55
  text "VBUS_STLK" at 1517,538 h55 r45
  text "I" at 2134,525 h551.18
  text "MB1811B" at 141,514 h80
  text "PG3" at 2425.83,492.87 h55
  text "E" at 2810,483 h551.18
  text "PA3" at 408,142 h55
  text "USER" at 1606.83,54.87 h55
  text "NRST" at 2303,52 h55
  text "POT" at 719.83,31.87 h55
  text ".Layer_Name" at 237.03,-1220.22 h118.11
  text ".GTO" at 1878.55,-1220.22 h118.11
Bottom Overlay:
  text "G" at 2144,428 h551.18
  text "F" at 1409,414 h551.18
  text "S" at 731,395 h450
  text ".GBO" at 1437.48,-1221.48 h118.11
  text ".Layer_Name" at 3064.02,-1221.48 h118.11
Top Paste:
  text ".Layer_Name" at 237.03,-1220.22 h118.11
  text ".GTP" at 1878.55,-1220.22 h118.11
Bottom Paste:
  text ".GBP" at 1437.48,-1221.48 h118.11
  text ".Layer_Name" at 3064.02,-1221.48 h118.11
Top Solder:
  text ".Layer_Name" at 237.03,-1220.22 h118.11
  text ".GTS" at 1878.55,-1220.22 h118.11
Bottom Solder:
  text ".GBS" at 1437.48,-1221.48 h118.11
  text ".Layer_Name" at 3064.02,-1221.48 h118.11
M1-Board Shape:
  lines w3.94: 3149.59,0 0,0 0,4291.34 3149.59,4291.34 3149.59,3805.13 ; 3150,0 3150,486.24
M2-Board Dimensions:
  text ".Layer_Name" at 237.03,-1220.22 h118.11
  text ".GM2" at 1878.55,-1220.22 h118.11
M4-Bottom Dimensions:
  lines w3.94: 3149.58,0.01 -0.01,0.01 -0.01,4291.35 3149.58,4291.35 3149.58,3805.14 ; 3149.99,0.01 3149.99,486.24
M7-Top Info:
  lines w1: -9080.14,-7480.29 -9030.14,-7480.29 ; -9055.14,-7505.29 -9055.14,-7455.29
M10-Bottom Stiffener:
  lines w0.39: 2732.81,807.9 3087.14,807.9 3087.14,1792.15 2732.81,1792.15 2732.81,807.9 ; 2732.81,1882.9 3087.14,1882.9 3087.14,2867.15 2732.81,2867.15 2732.81,1882.9
Mechanical 11:
  lines w0.39: 2724.94,800.02 3095.02,800.02 3095.02,1800.02 2724.94,1800.02 2724.94,800.02 ; 2724.94,1875.02 3095.02,1875.02 3095.02,2875.02 2724.94,2875.02 2724.94,1875.02
M14-Top Assembly:
  text ".Layer_Name" at 237.03,-1220.22 h118.11
  text ".GM14" at 1878.55,-1220.22 h118.11
M15-Bottom Assembly:
  text ".GM15" at 1437.48,-1221.48 h118.11
  text ".Layer_Name" at 3064.02,-1221.48 h118.11
Drill Drawing:
  drawing of 1049 lines, arcs and shapes, not listed
  text "6" at -2814,11465 h130
  text "6" at -2814,11465 h130
  text "5" at 686,11465 h130
  text "5" at 686,11465 h130
  text "4" at 4186,11465 h130
  text "4" at 4186,11465 h130
  text "3" at 7686,11465 h130
  text "3" at 7686,11465 h130
  text "2" at 11186,11465 h130
  text "2" at 11186,11465 h130
  text "1" at 14686,11465 h130
  text "1" at 14686,11465 h130
  text "REVISIONS" at 13424,11204 h90
  text "DESCRIPTION" at 12720,10977 h75
  text "DATA" at 15036,10977 h75
  text "APPROVED" at 15649,10971 h75
  text "REV" at 12311,10961 h75
  text "1.0" at 12303,10777 h75
  text "***" at 15719,10769 h75
  text "2008-**-**" at 14878,10763 h75
  text "EDITION ORIGINALE" at 12712,10761 h75
  text "D" at -4814,9165 h130
  text "D" at -4814,9165 h130
  text "D" at 16486,9165 h130
  text "D" at 16486,9165 h130
  text "H" at 7247.98,6955.09 h75
  text "H" at 7247.98,6955.09 h75
  text "LAYER STACK-UP" at 7447.98,6955.09 h75
  text "LAYER STACK-UP" at 7447.98,6955.09 h75
  text "SOLDERMASK & SILKSCREEN" at 9137.98,6770.09 h60
  text "SOLDERMASK & SILKSCREEN" at 9137.98,6770.09 h60
  text "5" at -232,6763 h100
  text "IMPEDANCE TABLE" at -1,6740 h100
  text "IMPEDANCE TABLE" at -1,6740 h100
  text "LAYER 1 (0.5 oz cu+plating)" at 9146.68,6630.79 h60
  text "LAYER 1 (0.5 oz cu+plating)" at 9146.68,6630.79 h60
  text "PREPREG  3.9 MIL" at 7837.98,6470.09 h60
  text "PREPREG  3.9 MIL" at 7837.98,6470.09 h60
  text "LAYER" at -76,6446 h75
  text "LAYER" at -76,6446 h75
  text "TOLERANCE" at 3674,6446 h75
  text "TOLERANCE" at 3674,6446 h75
  text "TRACE" at 674,6436 h75
  text "TRACE" at 674,6436 h75
  text "SPACEING" at 1224,6436 h75
  text "SPACEING" at 1224,6436 h75
  text "IMPEDANCE" at 1974,6436 h75
  text "IMPEDANCE" at 1974,6436 h75
  text "IMPEDANCE" at 2874,6436 h75
  text "IMPEDANCE" at 2874,6436 h75
  text "20" at 5250,6410.33 h50
  text "20" at 5250,6410.33 h50
  text "(mil)" at 724,6346 h50
  text "(mil)" at 724,6346 h50
  text "(Single end)" at 2024,6346 h50
  text "(Single end)" at 2024,6346 h50
  text "LAYER 2 (1 oz)" at 9137.98,6345.09 h60
  text "LAYER 2 (1 oz)" at 9137.98,6345.09 h60
  text "(mil)" at 1324,6336 h50
  text "(mil)" at 1324,6336 h50
  text "(Differential)" at 2874,6336 h50
  text "(Differential)" at 2874,6336 h50
  text "63 mil" at 7132.48,6302.59 h50
  text "63 mil" at 7132.48,6302.59 h50
  text "+/-10%" at 7137.98,6245.09 h40
  text "+/-10%" at 7137.98,6245.09 h40
  text "CORE" at 7827.98,6225.09 h60
  text "CORE" at 7827.98,6225.09 h60
  text "LAYER 3 (1 oz)" at 9137.98,6145.09 h60
  text "LAYER 3 (1 oz)" at 9137.98,6145.09 h60
  text "1,4" at -72,6143 h75
  text "N/A" at 1374,6136 h75
  text "N/A" at 1374,6136 h75
  text "5.0" at 728,6128 h75
  text "55 OHM" at 2024,6126 h75
  text "55 OHM" at 2024,6126 h75
  text "N/A" at 3024,6126 h75
  text "N/A" at 3024,6126 h75
  text "+/-10%" at 3774,6126 h75
  text "+/-10%" at 3774,6126 h75
  text "PREPREG  3.9 MIL" at 7837.98,5970.09 h60
  text "PREPREG  3.9 MIL" at 7837.98,5970.09 h60
  text "N/A" at 2129,5890 h75
  text "6.1" at 711,5885 h75
  text "90 OHM" at 2939,5880 h75
  text "+/-10%" at 3774,5876 h75
  text "+/-10%" at 3774,5876 h75
  text "1,4" at -67,5873 h75
  text "8.9" at 1353,5872 h75
  text "LAYER 4 (0.5 oz cu+plating)" at 9137.98,5820.09 h60
  text "LAYER 4 (0.5 oz cu+plating)" at 9137.98,5820.09 h60
  text "SOLDERMASK & SILKSCREEN" at 9137.98,5700.09 h60
  text "SOLDERMASK & SILKSCREEN" at 9137.98,5700.09 h60
  text "1.60MM" at 5748.5,5675.33 h50
  text "0.062" at 5728,5555.33 h50
  text "4 LAYER STACKING" at 7737.98,5555.09 h75
  text "4 LAYER STACKING" at 7737.98,5555.09 h75
  text "1.30MM" at 4965,5548.83 h50 r90
  text "1.30MM" at 4965,5548.83 h50 r90
  text "0.051" at 5085,5528.33 h50 r90
  text "0.051" at 5085,5528.33 h50 r90
  text "C" at -4814,5265 h130
  text "C" at -4814,5265 h130
  text "C" at 16486,5265 h130
  text "C" at 16486,5265 h130
  text "DETAIL B" at 5125,5160.33 h85
  text "DETAIL B" at 5125,5160.33 h85
  text "PCB SPECIFICATIONS :" at 4503.86,4000.21 h118.11
  text "PCB : TYPE 3" at 10310.62,3993.43 h118.11
  text "A.   MATERIAL :" at 4503.86,3842.73 h118.11
  text "FR-4" at 6019.61,3842.73 h118.11
  text "TG-170" at 6669.22,3842.73 h118.11
  text "X  TG-150" at 7387.72,3842.73 h118.11
  text "TG-140" at 8017.64,3842.73 h118.11
  text "ASPECT-RATIO, AXE Z :" at 10310.62,3776.89 h118.11
  text "B.   MATERIAL FAMILY :" at 4503.86,3724.62 h118.11
  text "N/A" at 6019.61,3724.62 h118.11
  text "C.   SOLDERMASK COLOR :" at 4503.86,3606.51 h118.11
  text "GREEN" at 6019.61,3606.51 h118.11
  text "WHITE" at 6669.22,3606.51 h118.11
  text "RED" at 7387.72,3606.51 h118.11
  text "BLACK" at 8017.64,3606.51 h118.11
  text "X  Blue ink PANTONE 2955" at 8677.03,3605 h118.11
  text "6:1 to 8:1" at 10311.36,3511.24 h118.11
  text "D.   SILKSCREEN COLOR :" at 4503.86,3488.4 h118.11
  text "X  WHITE" at 6019.61,3488.4 h118.11
  text "YELLOW" at 6669.22,3488.4 h118.11
  text "BLACK" at 7387.72,3488.4 h118.11
  text "Blue ink PANTONE 2955" at 8017.64,3488.4 h118.11
  text "E.   SURFACE FINISH :" at 4503.86,3370.29 h118.11
  text "X  ENIG" at 6019.61,3370.29 h118.11
  text "IMMERSION SILVER" at 6669.22,3370.29 h118.11
  text "IMMERSION TIN" at 8017.64,3370.29 h118.11
  text "MINIMUM PARAMETERS" at 10312.42,3290.73 h118.11
  text "HASL" at 6019.61,3252.18 h118.11
  text "HASL (PB-FREE)" at 6669.22,3252.18 h118.11
  text "GOLDEN FINGER" at 8017.64,3252.18 h118.11
  text "F.   IMPEDANCE CONTROL :" at 4503.86,3134.07 h118.11
  text "NO" at 6019.61,3134.07 h118.11
  text "X  YES  (SEE IMPEDANCE TABLE FOR DETAIL INFORMATION)" at 6669.22,3134.07 h118.11
  text "DEFAULT" at 10312.42,3074.19 h118.11
  text "G.   THROUGH VIA :" at 4503.86,3015.96 h118.11
  text "PLUG THE VIAS WHICH ARE COVERED WITH SOLDERMASK ONE OR TWO SIDE." at 6019.61,3015.96 h118.11
  text "PLUG MATERIAL :" at 6019.61,2897.85 h118.11
  text "X  SOLDERMASK" at 7023.55,2897.85 h118.11
  text "NON-CONDUCTIVE EPOXY." at 8017.64,2897.85 h118.11
  text "TRACKS : 0.127mm" at 10312.42,2847.82 h118.11
  text "H.   STACK-UP :" at 4503.86,2779.74 h118.11
  text "SEE LAYER STACK-UP SEQUENCE FOR OVERALL THICKNESS." at 6019.61,2779.74 h118.11
  text "Symbol" at 3955.5,2191.94 h72
  text "Count" at 4461.38,2191.94 h72
  text "Hole Size" at 5061.22,2191.94 h72
  text "Plated" at 6210.88,2191.94 h72
  text "Hole Type" at 6716.76,2191.94 h72
  text "Drill Layer Pair" at 7450.56,2191.94 h72
  text "Via/Pad" at 8950.11,2191.94 h72
  text "Pad Shape" at 9539.96,2191.94 h72
  text "Template" at 10285.76,2191.94 h72
  text "Description" at 12315.13,2191.94 h72
  text "Hole Tolerance (+)" at 13168.9,2191.94 h72
  text "Hole Tolerance (-)" at 14502.51,2191.94 h72
  text "3" at 4461.38,2041.94 h60
  text "31.50mil (0.800mm)" at 5061.22,2041.94 h60
  text "PTH" at 6210.88,2041.94 h60
  text "Round" at 6716.76,2041.94 h60
  text "Top Layer - Bottom Layer" at 7450.56,2041.94 h60
  text "Pad" at 8950.11,2041.94 h60
  text "(Mixed)" at 9539.96,2041.94 h60
  text "(Mixed)" at 10285.76,2041.94 h60
  text "4" at 4461.38,1891.94 h60
  text "17.72mil (0.450mm)" at 5061.22,1891.94 h60
  text "PTH" at 6210.88,1891.94 h60
  text "Slot" at 6716.76,1891.94 h60
  text "Top Layer - Bottom Layer" at 7450.56,1891.94 h60
  text "Pad" at 8950.11,1891.94 h60
  text "Rounded" at 9539.96,1891.94 h60
  text "r155_115h45_85r100m160_120(Tol5-5)" at 10285.76,1891.94 h60
  text "1.97mil (0.050mm)" at 13168.9,1891.94 h60
  text "1.97mil (0.050mm)" at 14502.51,1891.94 h60
  text "4" at 4461.38,1741.94 h60
  text "39.37mil (1.000mm)" at 5061.22,1741.94 h60
  text "NPTH" at 6210.88,1741.94 h60
  text "Round" at 6716.76,1741.94 h60
  text "Top Layer - Bottom Layer" at 7450.56,1741.94 h60
  text "Pad" at 8950.11,1741.94 h60
  text "Rounded" at 9539.96,1741.94 h60
  text "c0hn100m105p1000" at 10285.76,1741.94 h60
  text "4" at 4461.38,1591.94 h60
  text "137.80mil (3.500mm)" at 5061.22,1591.94 h60
  text "PTH" at 6210.88,1591.94 h60
  text "Round" at 6716.76,1591.94 h60
  text "Top Layer - Bottom Layer" at 7450.56,1591.94 h60
  text "Pad" at 8950.11,1591.94 h60
  text "Rounded" at 9539.96,1591.94 h60
  text "c600h350m605" at 10285.76,1591.94 h60
  text "B" at -4814,1565 h130
  text "B" at -4814,1565 h130
  text "B" at 16486,1565 h130
  text "B" at 16486,1565 h130
  text "14" at 4461.38,1441.94 h60
  text "15.75mil (0.400mm)" at 5061.22,1441.94 h60
  text "PTH" at 6210.88,1441.94 h60
  text "Round" at 6716.76,1441.94 h60
  text "Top Layer - Bottom Layer" at 7450.56,1441.94 h60
  text "Pad" at 8950.11,1441.94 h60
  text "Rounded" at 9539.96,1441.94 h60
  text "c60h40m65(Tol3-3)" at 10285.76,1441.94 h60
  text "1.18mil (0.030mm)" at 13168.9,1441.94 h60
  text "1.18mil (0.030mm)" at 14502.51,1441.94 h60
  text "72" at 4461.38,1291.94 h60
  text "8.00mil (0.203mm)" at 5061.22,1291.94 h60
  text "PTH" at 6210.88,1291.94 h60
  text "Round" at 6716.76,1291.94 h60
  text "Top Layer - Bottom Layer" at 7450.56,1291.94 h60
  text "Via" at 8950.11,1291.94 h60
  text "Rounded" at 9539.96,1291.94 h60
  text "v41h20m0mx0" at 10285.76,1291.94 h60
  text "93" at 4461.38,1141.94 h60
  text "39.37mil (1.000mm)" at 5061.22,1141.94 h60
  text "PTH" at 6210.88,1141.94 h60
  text "Round" at 6716.76,1141.94 h60
  text "Top Layer - Bottom Layer" at 7450.56,1141.94 h60
  text "Pad" at 8950.11,1141.94 h60
  text "Rounded" at 9539.96,1141.94 h60
  text "(Mixed)" at 10285.76,1141.94 h60
  text "509" at 4461.38,991.94 h60
  text "10.00mil (0.254mm)" at 5061.22,991.94 h60
  text "PTH" at 6210.88,991.94 h60
  text "Round" at 6716.76,991.94 h60
  text "Top Layer - Bottom Layer" at 7450.56,991.94 h60
  text "Via" at 8950.11,991.94 h60
  text "Rounded" at 9539.96,991.94 h60
  text "v51h25m0mx0" at 10285.76,991.94 h60
  text "703 Total" at 4461.38,841.94 h60
  text "Slot definitions :" at 3955.5,696.97 h60
  text "Routed Path Length" at 4988.19,696.97 h60
  text "= Calculated from tool start centre position to tool end centre position." at 6090.86,696.97 h60
  text "Hole Length" at 4988.19,596.99 h60
  text "= Routed Path Length + Tool Size = Slot length as defined in the PCB layout" at 5680.99,596.99 h60
  text ".Layer_Name" at 237.03,-1220.22 h118.11
  text ".DRL" at 1878.55,-1220.22 h118.11
  text "A" at -4814,-2635 h130
  text "A" at -4814,-2635 h130
  text "A" at 16486,-2635 h130
  text "A" at 16486,-2635 h130
  text "DATA" at 12470,-2930 h75
  text "UNLESS OTHERWISE SPECIFIED" at 9179,-2939 h75
  text "SIGNATURES" at 11106,-2960 h75
  text "COMPANY NAME" at 14478,-3056 h90
  text "LOGO" at 13154,-3063 h90
  text "DRAWN" at 11106,-3160 h75
  text "YY-MM-DD" at 12380,-3180 h75
  text "DIMENSIONS ARE IN INCHES" at 9186,-3203 h75
  text "TOLERANCES ON;" at 9186,-3367 h75
  text "CHECKED" at 11106,-3390 h75
  text "YY-MM-DD" at 12365,-3390 h75
  text "TITLE" at 13075,-3478 h75
  text "2 PL DECIMALS +" at 9186,-3524 h75
  text "ENGGRG" at 11111,-3575 h75
  text "YY-MM-DD" at 12375,-3580 h75
  text "PROJECT NAME  *" at 13697,-3612 h90
  text "3 PL DECIMALS +" at 9194,-3679 h75
  text "ISSUED" at 11106,-3769 h75
  text "ANGLES +" at 9179,-3845 h75
  text "SIZE   B" at 13062,-3915 h75
  text "DWG  NO   *******" at 13949,-3915 h75
  text "REV **" at 15777,-3921 h75
  text "FRACTIONS +" at 9179,-4002 h75
  text "SCALE  1:1" at 13069,-4147 h75
  text "SHEET    1  OF  1" at 15009,-4153 h75
  text "6" at -2814,-4435 h130
  text "6" at -2814,-4435 h130
  text "5" at 686,-4435 h130
  text "5" at 686,-4435 h130
  text "4" at 4186,-4435 h130
  text "4" at 4186,-4435 h130
  text "3" at 7686,-4435 h130
  text "3" at 7686,-4435 h130
  text "2" at 11186,-4435 h130
  text "2" at 11186,-4435 h130
  text "1" at 14686,-4435 h130
  text "1" at 14686,-4435 h130
M20-Top Title Box:
  circle w10: c3308.06,-1484.81 r51.18
  region: 2738.06,-1527.85 2314.59,-1527.85 2353.7,-1429.71 2663.06,-1429.71 2680.72,-1399.81 2767.68,-1500.14
  region: 3289.36,-1199.92 2678.06,-1199.92 2650.72,-1269.81 2603.06,-1318.04 2548.06,-1244.81 2548.06,-1179.81 2593.06,-1124.81 2649.59,-1109.92 3289.36,-1109.92
  lines w10: 2353.7,-1429.71 2699.84,-1429.71 2579.12,-1290.42 cw(c2650.14,-1213.89) 2659.59,-1109.92 3319.59,-1109.92 3289.59,-1199.92 ; 2484.16,-1100.18 cw(c2579.68,-1138.39) 2588.99,-1035.94 ; 2485.7,-1098.91 2314.59,-1527.85 3075.32,-1527.85 ccw(c3085.11,-1420.2) 3185.48,-1460.34 ; 2554.2,-1253.82 2767.68,-1500.14 ; 2564.2,-1253.82 2773.06,-1494.81 ; 2564.2,-1243.82 2773.06,-1484.81 ; 2568.06,-1199.92 3079.59,-1199.92 ; 2569.2,-1238.82 2778.06,-1479.81 ; 2574.2,-1233.82 2783.06,-1474.81 ; 2579.2,-1228.82 2788.06,-1469.81 ; 2584.2,-1223.82 2793.06,-1464.81 ; 2586.35,-1146.95 2795.21,-1387.94 ; 2589.04,-1035.94 3354.78,-1035.94 3185.52,-1460.25 ; 2589.2,-1218.82 2795.91,-1457.34 ; 2589.2,-1208.82 2798.06,-1449.81 ; 2589.2,-1198.82 2798.06,-1439.81 ; 2589.2,-1163.82 2798.06,-1404.81 ; 2594.2,-1193.82 2803.06,-1434.81 ; 2594.2,-1178.82 2803.06,-1419.81 ; 2648.2,-1430.23 ccw(c2652.34,-1409.16) 2664.06,-1391.17 ; 2690.98,-1199.39 ccw(c2689.96,-1221.73) 2676.95,-1239.92 2770.06,-1347.35 cw(c2699.04,-1423.88) 2727.89,-1524.22 ; 2938.27,-1519.81 3052.03,-1189.92 ; 2947.03,-1517.85 3059.99,-1190.26 ; 2952.03,-1517.85 3064.99,-1190.26 ; 2962.03,-1517.85 3074.99,-1190.26 ; 2972.03,-1517.85 3084.99,-1190.26 ; 2982.03,-1517.85 3094.99,-1190.26 ; 2992.03,-1517.85 3104.99,-1190.26 ; 3002.03,-1517.85 3114.99,-1190.26 ; 3012.03,-1517.85 3124.99,-1190.26 ; 3022.03,-1517.85 3134.99,-1190.26 ; 3030.24,-1519.81 3144,-1189.92 ; 3144,-1199.92 3289.36,-1199.92 ; 3263.06,-1199.81 3293.06,-1109.81 ; 3269.59,-1199.92 3299.59,-1109.92 ; 3279.59,-1199.92 3309.59,-1109.92
  lines w11.81: -117.31,-1680.85 3426,-1680.85 3426,-893.45 -117.31,-893.45 ; -117.31,-1484 2244.89,-1484 ; -117.31,-1287.15 2244.89,-1287.15 ; -117.31,-1090.3 2244.89,-1090.3 ; -117.29,-1680.85 -117.29,-893.45 ; 1457.49,-1680.85 1457.49,-1090.3 ; 2244.89,-1680.85 2244.89,-893.45 ; 2938.27,-1519.81 3030.24,-1519.81
  text "Project: '.Board_Name'" at -77.93,-1020.06 h118.11
  text "Layer:" at -77.92,-1220.22 h118.11
  text "Gerber:" at 1496.43,-1220.22 h118.11
  text "Variant: '.VariantName'" at -77.93,-1417.07 h118.11
  text "Ref: '.Board_Reference'" at 1501.43,-1417.07 h118.11
  text "R" at 3288.06,-1514.81 h60
  text "Date: '.Board_Document_Date'" at -77.93,-1613.92 h118.11
  text "Rev: '.Board_PCB_Revision'" at 1499.18,-1613.92 h118.11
